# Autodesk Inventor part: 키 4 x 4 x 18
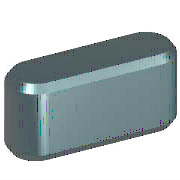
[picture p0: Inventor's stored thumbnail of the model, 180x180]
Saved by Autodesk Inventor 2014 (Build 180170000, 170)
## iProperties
IsCustomPart: 1
Created: 2012-02
Part Number: 키 4 x 4 x 18
Material: 강철, 연강
Description: 키 및 해당 키홈
Document SubType Name: Modeling
Standard: KS B 1311
Designer: mduedu
Standards Organization: KS
Language: ko-KR
Size Designation: 4 x 4 x 18
Categories: <MemberInstance><Categories><Category DisplayName="샤프트 부품" InternalName="7f7aeb1f-a693-4053-b835-cee3144e0d98" Mnemonic="SHFT"><Category DisplayName="키" Interna
Density: 7.86 g/cm^3
Mass: 2.13606 g
Surface Area: 2.87354 cm^2
Volume: 0.271763 cm^3
Appearance: 노란색
Author: mduedu
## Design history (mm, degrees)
workplane "Work Plane1"
workplane "Work Plane2"
sketch "스케치1"
  geometry: L1 (2, 2)-(16, 2); L2 (16, -2)-(2, -2); L3 (0, 9.4)-(0, -7.4) reference; L4 (-5, 0)-(30, 0) reference; L5 (18, 0)-(18, 7); A1 r 2 centre (2, 0) between (2, 2) and (2, -2); A2 r 2 centre (16, 0) between (16, -2) and (16, 2)
  constraints: 6 end point, 5 point on circle, 4 tangent, 3 point on line, 2 centre point, 1 horizontal, 1 parallel, 1 perpendicular
  dimensions: "d0" = 2 radius of A1 (= 0.5 x PB); "d13" = 2 radius of A2 (= 0.5 x PB); "d14" = 18 distance between parallel lines of L5 L3 (= NLG)
extrude "본체1" new body sketch "스케치1" taper "d3" = 0 deg; stored distance "d4" = 10
workplane "Work Plane3"
body "Solid1"
chamfer "모따기1" distance "d8" = 0.25 (= PHH); stored, may be unused: second distance "d9" = 0.25 (= PHH), angle "d15" = 45 deg
other parameters: "d1" = -2.5 (= -PNT), "d2" = 1.5 (= PH - PNT), "NLG" = 18 [user parameter; used in 3 equation terms], "PB" = 4 [user parameter; used in 2 equation terms], "PNT" = 2.5 [user parameter; used in 2 equation terms], "PH" = 4 [user parameter; used in 1 equation term], "PHH" = 0.25 [user parameter; used in 2 equation terms], "d10" = 0, "d16" = 0, "d17" = 0, "d18" = 0, "PLB2" = 18 (= NLG) [user parameter], "WDMAX" = 12 [user parameter], "PLB1" = 18 (= NLG) [user parameter], "RR" = 0.08 [user parameter], "PUEB" = 1.8 [user parameter]
